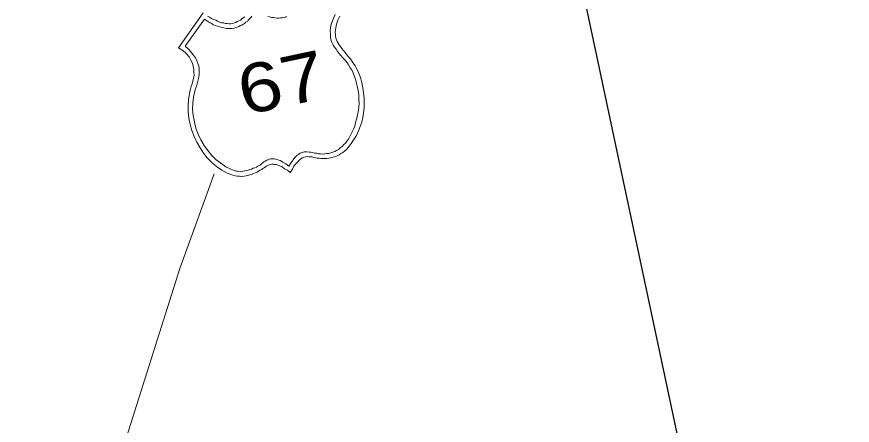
# Model space of a CAD drawing. Extents: x 2357218 to 2371708, y 6973728 to 6980157.
# Drawn here: x 2371620.9 to 2371708, y 6977542.6 to 6977585.2 of the extents above; entities that cross this region are included whole.
import ezdxf

# ---------------------------------------------------------------- set-up
doc = ezdxf.new("R2010")
doc.units = 0
doc.header["$LTSCALE"] = 2
doc.layers.add('62', color=7, linetype='Continuous', lineweight=13)
doc.layers.add('63', color=7, linetype='Continuous', lineweight=13)

msp = doc.modelspace()

# ---------------------------------------------------------------- linework, layer by layer
at = {"layer": '62', "lineweight": 25}
msp.add_lwpolyline([(2371171.482, 6977817.538), (2371268.218, 6977362.432), (2371707.985, 6977455.907), (2371611.249, 6977911.015)], dxfattribs=at)
at = {"layer": '62'}
for points in [[(2371637.751, 6977581.997), (2371640.317, 6977585.624)], [(2371640.753, 6977585.302), (2371640.983, 6977585.191), (2371641.195, 6977585.052), (2371641.403, 6977584.957), (2371641.626, 6977584.868), (2371641.809, 6977584.768), (2371642.035, 6977584.678), (2371642.234, 6977584.606), (2371642.426, 6977584.578), (2371642.643, 6977584.532), (2371642.828, 6977584.526), (2371643.039, 6977584.502), (2371643.204, 6977584.489), (2371643.403, 6977584.532), (2371643.594, 6977584.598), (2371643.721, 6977584.644), (2371643.861, 6977584.744), (2371644.032, 6977584.805), (2371644.199, 6977584.886), (2371644.358, 6977585.011), (2371644.497, 6977585.11), (2371644.654, 6977585.234)], [(2371645.382, 6977585.275), (2371645.272, 6977585.136), (2371645.16, 6977585.02), (2371645.009, 6977584.874), (2371644.923, 6977584.74), (2371644.754, 6977584.66), (2371644.62, 6977584.539), (2371644.473, 6977584.46), (2371644.335, 6977584.363), (2371644.185, 6977584.307), (2371644.023, 6977584.204), (2371643.875, 6977584.15), (2371643.723, 6977584.093), (2371643.551, 6977584.036), (2371643.332, 6977583.989), (2371643.149, 6977583.995), (2371642.917, 6977583.993), (2371642.705, 6977584.016), (2371642.465, 6977584.057), (2371642.229, 6977584.099), (2371642.049, 6977584.177), (2371641.807, 6977584.238), (2371641.586, 6977584.306), (2371641.382, 6977584.401), (2371641.195, 6977584.523), (2371640.969, 6977584.614), (2371640.777, 6977584.757)], [(2371649.019, 6977585.266), (2371648.895, 6977585.194), (2371648.741, 6977585.159), (2371648.587, 6977585.127), (2371648.384, 6977585.108), (2371648.205, 6977585.094), (2371648.022, 6977585.078), (2371647.809, 6977585.1), (2371647.642, 6977585.134), (2371647.431, 6977585.159), (2371647.236, 6977585.21), (2371647.067, 6977585.243)], [(2371655.858, 6977573.216), (2371655.981, 6977573.496), (2371656.119, 6977573.826), (2371656.208, 6977574.166), (2371656.316, 6977574.534), (2371656.392, 6977574.918), (2371656.469, 6977575.325), (2371656.537, 6977575.756), (2371656.564, 6977576.174), (2371656.559, 6977576.632), (2371656.53, 6977577.086), (2371656.482, 6977577.535), (2371656.383, 6977577.998), (2371656.259, 6977578.478), (2371656.125, 6977578.887), (2371655.996, 6977579.273), (2371655.835, 6977579.607), (2371655.653, 6977579.914), (2371655.478, 6977580.198), (2371655.281, 6977580.479), (2371655.094, 6977580.715), (2371654.882, 6977580.944), (2371654.673, 6977581.178), (2371654.51, 6977581.395), (2371654.327, 6977581.609), (2371654.167, 6977581.828), (2371654.006, 6977582.046), (2371653.887, 6977582.276), (2371653.774, 6977582.481), (2371653.673, 6977582.736), (2371653.607, 6977583.045), (2371653.576, 6977583.404), (2371653.574, 6977583.75), (2371653.59, 6977584.097), (2371653.653, 6977584.455), (2371653.785, 6977584.806), (2371653.923, 6977585.136), (2371654.08, 6977585.468)], [(2371654.561, 6977585.273), (2371654.346, 6977584.881), (2371654.226, 6977584.464), (2371654.153, 6977584.057), (2371654.08, 6977583.65), (2371654.108, 6977583.288), (2371654.149, 6977582.998), (2371654.211, 6977582.803), (2371654.272, 6977582.632), (2371654.397, 6977582.477), (2371654.482, 6977582.286), (2371654.634, 6977582.111), (2371654.79, 6977581.916), (2371654.95, 6977581.718), (2371655.109, 6977581.499), (2371655.298, 6977581.265), (2371655.483, 6977581.051), (2371655.665, 6977580.837), (2371655.836, 6977580.574), (2371655.997, 6977580.355), (2371656.163, 6977580.112), (2371656.281, 6977579.885), (2371656.422, 6977579.663), (2371656.5, 6977579.404), (2371656.705, 6977578.872), (2371656.867, 6977578.33), (2371656.972, 6977577.823), (2371657.039, 6977577.287), (2371657.102, 6977576.772), (2371657.102, 6977576.243), (2371657.093, 6977575.734), (2371657.044, 6977575.216), (2371656.966, 6977574.718), (2371656.841, 6977574.231)], [(2371640.454, 6977584.986), (2371638.433, 6977582.142), (2371638.798, 6977581.829), (2371639.071, 6977581.519), (2371639.317, 6977581.226), (2371639.516, 6977580.946), (2371639.652, 6977580.631), (2371639.778, 6977580.357), (2371639.879, 6977580.103), (2371639.897, 6977579.807), (2371639.891, 6977579.508), (2371639.902, 6977579.232), (2371639.875, 6977578.928), (2371639.798, 6977578.637), (2371639.742, 6977578.372), (2371639.665, 6977578.078), (2371639.562, 6977577.806), (2371639.465, 6977577.508), (2371639.304, 6977576.853), (2371639.238, 6977576.194), (2371639.209, 6977575.568), (2371639.278, 6977574.915), (2371639.398, 6977574.248), (2371639.559, 6977573.595), (2371639.804, 6977572.979), (2371640.09, 6977572.395), (2371640.423, 6977571.798), (2371640.814, 6977571.261), (2371641.223, 6977570.749), (2371641.687, 6977570.298), (2371642.156, 6977569.938), (2371642.671, 6977569.563), (2371643.208, 6977569.31), (2371643.758, 6977569.105), (2371643.873, 6977569.106), (2371643.998, 6977569.064), (2371644.16, 6977569.051), (2371644.338, 6977569.09), (2371644.469, 6977569.118), (2371644.652, 6977569.133), (2371644.826, 6977569.17), (2371644.998, 6977569.229), (2371645.195, 6977569.272), (2371645.371, 6977569.308), (2371645.533, 6977569.412), (2371645.704, 6977569.472), (2371645.876, 6977569.532), (2371646.016, 6977569.631), (2371646.162, 6977569.707), (2371646.283, 6977569.779), (2371646.419, 6977569.899), (2371646.536, 6977569.994), (2371646.655, 6977570.088), (2371646.777, 6977570.159), (2371646.939, 6977570.262), (2371647.046, 6977570.308), (2371647.194, 6977570.364), (2371647.348, 6977570.397), (2371647.509, 6977570.408), (2371647.736, 6977570.41), (2371647.905, 6977570.375), (2371648.11, 6977570.283), (2371648.353, 6977570.219), (2371648.621, 6977570.046), (2371648.93, 6977569.882), (2371649.233, 6977569.647), (2371649.475, 6977570.019), (2371649.694, 6977570.297), (2371649.873, 6977570.541), (2371650.081, 6977570.747), (2371650.283, 6977570.882), (2371650.443, 6977570.986), (2371650.632, 6977571.071), (2371650.831, 6977571.114), (2371651.012, 6977571.129), (2371651.171, 6977571.14), (2371651.359, 6977571.111), (2371651.551, 6977571.083), (2371651.739, 6977571.055), (2371651.913, 6977570.997), (2371652.124, 6977570.975), (2371652.343, 6977570.929), (2371652.55, 6977570.927), (2371652.766, 6977570.881), (2371652.987, 6977570.928), (2371653.189, 6977570.948), (2371653.413, 6977570.971), (2371653.629, 6977571.041), (2371653.822, 6977571.106), (2371654.039, 6977571.173), (2371654.22, 6977571.283), (2371654.434, 6977571.374), (2371654.604, 6977571.547), (2371654.804, 6977571.681), (2371654.954, 6977571.85), (2371655.145, 6977572.03), (2371655.305, 6977572.249), (2371655.465, 6977572.467), (2371655.58, 6977572.676), (2371655.707, 6977572.955), (2371655.858, 6977573.216)], [(2371640.777, 6977584.757), (2371640.612, 6977584.881), (2371640.454, 6977584.986)], [(2371638.547, 6977581.384), (2371638.204, 6977581.701), (2371637.751, 6977581.997)], [(2371656.841, 6977574.231), (2371656.685, 6977573.762), (2371656.505, 6977573.309), (2371656.306, 6977572.851), (2371656.033, 6977572.404), (2371655.749, 6977571.999), (2371655.445, 6977571.589), (2371655.257, 6977571.387), (2371655.066, 6977571.208), (2371654.868, 6977571.052), (2371654.663, 6977570.941), (2371654.484, 6977570.81), (2371654.273, 6977570.717), (2371654.04, 6977570.621), (2371653.849, 6977570.558), (2371653.632, 6977570.489), (2371653.406, 6977570.465), (2371653.211, 6977570.424), (2371653.002, 6977570.423), (2371652.769, 6977570.445), (2371652.586, 6977570.429), (2371652.398, 6977570.458), (2371652.206, 6977570.485), (2371652.016, 6977570.514), (2371651.847, 6977570.548), (2371651.675, 6977570.605), (2371651.51, 6977570.613), (2371651.348, 6977570.626), (2371651.163, 6977570.632), (2371651.004, 6977570.62), (2371650.828, 6977570.583), (2371650.661, 6977570.501), (2371650.499, 6977570.398), (2371650.324, 6977570.247), (2371650.172, 6977570.1), (2371649.967, 6977569.87), (2371649.784, 6977569.651), (2371649.62, 6977569.336), (2371649.395, 6977568.99), (2371649.097, 6977569.203), (2371648.809, 6977569.373), (2371648.564, 6977569.552), (2371648.337, 6977569.639), (2371648.133, 6977569.734), (2371647.933, 6977569.808), (2371647.77, 6977569.818), (2371647.603, 6977569.852), (2371647.463, 6977569.845), (2371647.311, 6977569.814), (2371647.204, 6977569.767), (2371647.06, 6977569.692), (2371646.934, 6977569.642), (2371646.81, 6977569.569), (2371646.672, 6977569.47), (2371646.527, 6977569.394), (2371646.432, 6977569.303), (2371646.264, 6977569.223), (2371646.103, 6977569.118), (2371645.94, 6977569.016), (2371645.746, 6977568.95), (2371645.581, 6977568.869), (2371645.369, 6977568.78), (2371645.198, 6977568.72), (2371644.977, 6977568.673), (2371644.801, 6977568.636), (2371644.582, 6977568.588), (2371644.334, 6977568.56), (2371644.123, 6977568.584), (2371643.892, 6977568.581), (2371643.655, 6977568.62), (2371643.41, 6977568.687), (2371642.835, 6977568.908), (2371642.259, 6977569.223), (2371641.721, 6977569.59), (2371641.218, 6977570.012), (2371640.749, 6977570.489), (2371640.346, 6977570.977), (2371639.994, 6977571.546), (2371639.661, 6977572.144), (2371639.397, 6977572.732), (2371639.15, 6977573.347), (2371638.968, 6977573.998), (2371638.833, 6977574.636), (2371638.757, 6977575.308), (2371638.742, 6977575.929), (2371638.787, 6977576.58), (2371638.885, 6977577.2), (2371638.924, 6977577.438), (2371638.989, 6977577.682), (2371639.07, 6977577.953), (2371639.173, 6977578.229), (2371639.227, 6977578.514), (2371639.302, 6977578.806), (2371639.376, 6977579.12), (2371639.356, 6977579.416), (2371639.357, 6977579.74), (2371639.287, 6977580.069), (2371639.221, 6977580.378), (2371639.037, 6977580.706), (2371638.851, 6977581.035), (2371638.547, 6977581.384)], [(2371641.471, 6977568.825), (2371637.889, 6977558.952), (2371632.104, 6977540.699), (2371630.059, 6977521.101), (2371629.958, 6977506.428), (2371616.354, 6977490.125), (2371618.311, 6977480.254), (2371604.289, 6977467.66), (2371593.247, 6977456.295), (2371579.034, 6977445.889), (2371557.99, 6977437.089), (2371540.234, 6977428.852), (2371521.019, 6977419.249), (2371509.386, 6977413.693)]]:
    msp.add_lwpolyline(points, dxfattribs=at)
at = {"layer": '63', "lineweight": 25}
msp.add_lwpolyline([(2371171.482, 6977817.538), (2371268.218, 6977362.432), (2371707.985, 6977455.907), (2371611.249, 6977911.015)], dxfattribs=at)
at = {"layer": '63'}
for points in [[(2371637.751, 6977581.997), (2371640.317, 6977585.624)], [(2371640.753, 6977585.302), (2371640.983, 6977585.191), (2371641.195, 6977585.052), (2371641.403, 6977584.957), (2371641.626, 6977584.868), (2371641.809, 6977584.768), (2371642.035, 6977584.678), (2371642.234, 6977584.606), (2371642.426, 6977584.578), (2371642.643, 6977584.532), (2371642.828, 6977584.526), (2371643.039, 6977584.502), (2371643.204, 6977584.489), (2371643.403, 6977584.532), (2371643.594, 6977584.598), (2371643.721, 6977584.644), (2371643.861, 6977584.744), (2371644.032, 6977584.805), (2371644.199, 6977584.886), (2371644.358, 6977585.011), (2371644.497, 6977585.11), (2371644.654, 6977585.234)], [(2371645.382, 6977585.275), (2371645.272, 6977585.136), (2371645.16, 6977585.02), (2371645.009, 6977584.874), (2371644.923, 6977584.74), (2371644.754, 6977584.66), (2371644.62, 6977584.539), (2371644.473, 6977584.46), (2371644.335, 6977584.363), (2371644.185, 6977584.307), (2371644.023, 6977584.204), (2371643.875, 6977584.15), (2371643.723, 6977584.093), (2371643.551, 6977584.036), (2371643.332, 6977583.989), (2371643.149, 6977583.995), (2371642.917, 6977583.993), (2371642.705, 6977584.016), (2371642.465, 6977584.057), (2371642.229, 6977584.099), (2371642.049, 6977584.177), (2371641.807, 6977584.238), (2371641.586, 6977584.306), (2371641.382, 6977584.401), (2371641.195, 6977584.523), (2371640.969, 6977584.614), (2371640.777, 6977584.757)], [(2371649.019, 6977585.266), (2371648.895, 6977585.194), (2371648.741, 6977585.159), (2371648.587, 6977585.127), (2371648.384, 6977585.108), (2371648.205, 6977585.094), (2371648.022, 6977585.078), (2371647.809, 6977585.1), (2371647.642, 6977585.134), (2371647.431, 6977585.159), (2371647.236, 6977585.21), (2371647.067, 6977585.243)], [(2371655.858, 6977573.216), (2371655.981, 6977573.496), (2371656.119, 6977573.826), (2371656.208, 6977574.166), (2371656.316, 6977574.534), (2371656.392, 6977574.918), (2371656.469, 6977575.325), (2371656.537, 6977575.756), (2371656.564, 6977576.174), (2371656.559, 6977576.632), (2371656.53, 6977577.086), (2371656.482, 6977577.535), (2371656.383, 6977577.998), (2371656.259, 6977578.478), (2371656.125, 6977578.887), (2371655.996, 6977579.273), (2371655.835, 6977579.607), (2371655.653, 6977579.914), (2371655.478, 6977580.198), (2371655.281, 6977580.479), (2371655.094, 6977580.715), (2371654.882, 6977580.944), (2371654.673, 6977581.178), (2371654.51, 6977581.395), (2371654.327, 6977581.609), (2371654.167, 6977581.828), (2371654.006, 6977582.046), (2371653.887, 6977582.276), (2371653.774, 6977582.481), (2371653.673, 6977582.736), (2371653.607, 6977583.045), (2371653.576, 6977583.404), (2371653.574, 6977583.75), (2371653.59, 6977584.097), (2371653.653, 6977584.455), (2371653.785, 6977584.806), (2371653.923, 6977585.136), (2371654.08, 6977585.468)], [(2371654.561, 6977585.273), (2371654.346, 6977584.881), (2371654.226, 6977584.464), (2371654.153, 6977584.057), (2371654.08, 6977583.65), (2371654.108, 6977583.288), (2371654.149, 6977582.998), (2371654.211, 6977582.803), (2371654.272, 6977582.632), (2371654.397, 6977582.477), (2371654.482, 6977582.286), (2371654.634, 6977582.111), (2371654.79, 6977581.916), (2371654.95, 6977581.718), (2371655.109, 6977581.499), (2371655.298, 6977581.265), (2371655.483, 6977581.051), (2371655.665, 6977580.837), (2371655.836, 6977580.574), (2371655.997, 6977580.355), (2371656.163, 6977580.112), (2371656.281, 6977579.885), (2371656.422, 6977579.663), (2371656.5, 6977579.404), (2371656.705, 6977578.872), (2371656.867, 6977578.33), (2371656.972, 6977577.823), (2371657.039, 6977577.287), (2371657.102, 6977576.772), (2371657.102, 6977576.243), (2371657.093, 6977575.734), (2371657.044, 6977575.216), (2371656.966, 6977574.718), (2371656.841, 6977574.231)], [(2371640.454, 6977584.986), (2371638.433, 6977582.142), (2371638.798, 6977581.829), (2371639.071, 6977581.519), (2371639.317, 6977581.226), (2371639.516, 6977580.946), (2371639.652, 6977580.631), (2371639.778, 6977580.357), (2371639.879, 6977580.103), (2371639.897, 6977579.807), (2371639.891, 6977579.508), (2371639.902, 6977579.232), (2371639.875, 6977578.928), (2371639.798, 6977578.637), (2371639.742, 6977578.372), (2371639.665, 6977578.078), (2371639.562, 6977577.806), (2371639.465, 6977577.508), (2371639.304, 6977576.853), (2371639.238, 6977576.194), (2371639.209, 6977575.568), (2371639.278, 6977574.915), (2371639.398, 6977574.248), (2371639.559, 6977573.595), (2371639.804, 6977572.979), (2371640.09, 6977572.395), (2371640.423, 6977571.798), (2371640.814, 6977571.261), (2371641.223, 6977570.749), (2371641.687, 6977570.298), (2371642.156, 6977569.938), (2371642.671, 6977569.563), (2371643.208, 6977569.31), (2371643.758, 6977569.105), (2371643.873, 6977569.106), (2371643.998, 6977569.064), (2371644.16, 6977569.051), (2371644.338, 6977569.09), (2371644.469, 6977569.118), (2371644.652, 6977569.133), (2371644.826, 6977569.17), (2371644.998, 6977569.229), (2371645.195, 6977569.272), (2371645.371, 6977569.308), (2371645.533, 6977569.412), (2371645.704, 6977569.472), (2371645.876, 6977569.532), (2371646.016, 6977569.631), (2371646.162, 6977569.707), (2371646.283, 6977569.779), (2371646.419, 6977569.899), (2371646.536, 6977569.994), (2371646.655, 6977570.088), (2371646.777, 6977570.159), (2371646.939, 6977570.262), (2371647.046, 6977570.308), (2371647.194, 6977570.364), (2371647.348, 6977570.397), (2371647.509, 6977570.408), (2371647.736, 6977570.41), (2371647.905, 6977570.375), (2371648.11, 6977570.283), (2371648.353, 6977570.219), (2371648.621, 6977570.046), (2371648.93, 6977569.882), (2371649.233, 6977569.647), (2371649.475, 6977570.019), (2371649.694, 6977570.297), (2371649.873, 6977570.541), (2371650.081, 6977570.747), (2371650.283, 6977570.882), (2371650.443, 6977570.986), (2371650.632, 6977571.071), (2371650.831, 6977571.114), (2371651.012, 6977571.129), (2371651.171, 6977571.14), (2371651.359, 6977571.111), (2371651.551, 6977571.083), (2371651.739, 6977571.055), (2371651.913, 6977570.997), (2371652.124, 6977570.975), (2371652.343, 6977570.929), (2371652.55, 6977570.927), (2371652.766, 6977570.881), (2371652.987, 6977570.928), (2371653.189, 6977570.948), (2371653.413, 6977570.971), (2371653.629, 6977571.041), (2371653.822, 6977571.106), (2371654.039, 6977571.173), (2371654.22, 6977571.283), (2371654.434, 6977571.374), (2371654.604, 6977571.547), (2371654.804, 6977571.681), (2371654.954, 6977571.85), (2371655.145, 6977572.03), (2371655.305, 6977572.249), (2371655.465, 6977572.467), (2371655.58, 6977572.676), (2371655.707, 6977572.955), (2371655.858, 6977573.216)], [(2371640.777, 6977584.757), (2371640.612, 6977584.881), (2371640.454, 6977584.986)], [(2371638.547, 6977581.384), (2371638.204, 6977581.701), (2371637.751, 6977581.997)], [(2371656.841, 6977574.231), (2371656.685, 6977573.762), (2371656.505, 6977573.309), (2371656.306, 6977572.851), (2371656.033, 6977572.404), (2371655.749, 6977571.999), (2371655.445, 6977571.589), (2371655.257, 6977571.387), (2371655.066, 6977571.208), (2371654.868, 6977571.052), (2371654.663, 6977570.941), (2371654.484, 6977570.81), (2371654.273, 6977570.717), (2371654.04, 6977570.621), (2371653.849, 6977570.558), (2371653.632, 6977570.489), (2371653.406, 6977570.465), (2371653.211, 6977570.424), (2371653.002, 6977570.423), (2371652.769, 6977570.445), (2371652.586, 6977570.429), (2371652.398, 6977570.458), (2371652.206, 6977570.485), (2371652.016, 6977570.514), (2371651.847, 6977570.548), (2371651.675, 6977570.605), (2371651.51, 6977570.613), (2371651.348, 6977570.626), (2371651.163, 6977570.632), (2371651.004, 6977570.62), (2371650.828, 6977570.583), (2371650.661, 6977570.501), (2371650.499, 6977570.398), (2371650.324, 6977570.247), (2371650.172, 6977570.1), (2371649.967, 6977569.87), (2371649.784, 6977569.651), (2371649.62, 6977569.336), (2371649.395, 6977568.99), (2371649.097, 6977569.203), (2371648.809, 6977569.373), (2371648.564, 6977569.552), (2371648.337, 6977569.639), (2371648.133, 6977569.734), (2371647.933, 6977569.808), (2371647.77, 6977569.818), (2371647.603, 6977569.852), (2371647.463, 6977569.845), (2371647.311, 6977569.814), (2371647.204, 6977569.767), (2371647.06, 6977569.692), (2371646.934, 6977569.642), (2371646.81, 6977569.569), (2371646.672, 6977569.47), (2371646.527, 6977569.394), (2371646.432, 6977569.303), (2371646.264, 6977569.223), (2371646.103, 6977569.118), (2371645.94, 6977569.016), (2371645.746, 6977568.95), (2371645.581, 6977568.869), (2371645.369, 6977568.78), (2371645.198, 6977568.72), (2371644.977, 6977568.673), (2371644.801, 6977568.636), (2371644.582, 6977568.588), (2371644.334, 6977568.56), (2371644.123, 6977568.584), (2371643.892, 6977568.581), (2371643.655, 6977568.62), (2371643.41, 6977568.687), (2371642.835, 6977568.908), (2371642.259, 6977569.223), (2371641.721, 6977569.59), (2371641.218, 6977570.012), (2371640.749, 6977570.489), (2371640.346, 6977570.977), (2371639.994, 6977571.546), (2371639.661, 6977572.144), (2371639.397, 6977572.732), (2371639.15, 6977573.347), (2371638.968, 6977573.998), (2371638.833, 6977574.636), (2371638.757, 6977575.308), (2371638.742, 6977575.929), (2371638.787, 6977576.58), (2371638.885, 6977577.2), (2371638.924, 6977577.438), (2371638.989, 6977577.682), (2371639.07, 6977577.953), (2371639.173, 6977578.229), (2371639.227, 6977578.514), (2371639.302, 6977578.806), (2371639.376, 6977579.12), (2371639.356, 6977579.416), (2371639.357, 6977579.74), (2371639.287, 6977580.069), (2371639.221, 6977580.378), (2371639.037, 6977580.706), (2371638.851, 6977581.035), (2371638.547, 6977581.384)], [(2371641.471, 6977568.825), (2371637.889, 6977558.952), (2371632.104, 6977540.699), (2371630.059, 6977521.101), (2371629.958, 6977506.428), (2371616.354, 6977490.125), (2371618.311, 6977480.254), (2371604.289, 6977467.66), (2371593.247, 6977456.295), (2371579.034, 6977445.889), (2371557.99, 6977437.089), (2371540.234, 6977428.852), (2371521.019, 6977419.249), (2371509.386, 6977413.693)]]:
    msp.add_lwpolyline(points, dxfattribs=at)

# ---------------------------------------------------------------- texts
at = {"layer": '62', "width": 1.2}
msp.add_text('67', height=5.099, rotation=12, dxfattribs=at).set_placement((2371644.544, 6977574.931))
at = {"layer": '63', "width": 1.2}
msp.add_text('67', height=5.099, rotation=12, dxfattribs=at).set_placement((2371644.544, 6977574.931))

doc.saveas('drawing.dxf')
